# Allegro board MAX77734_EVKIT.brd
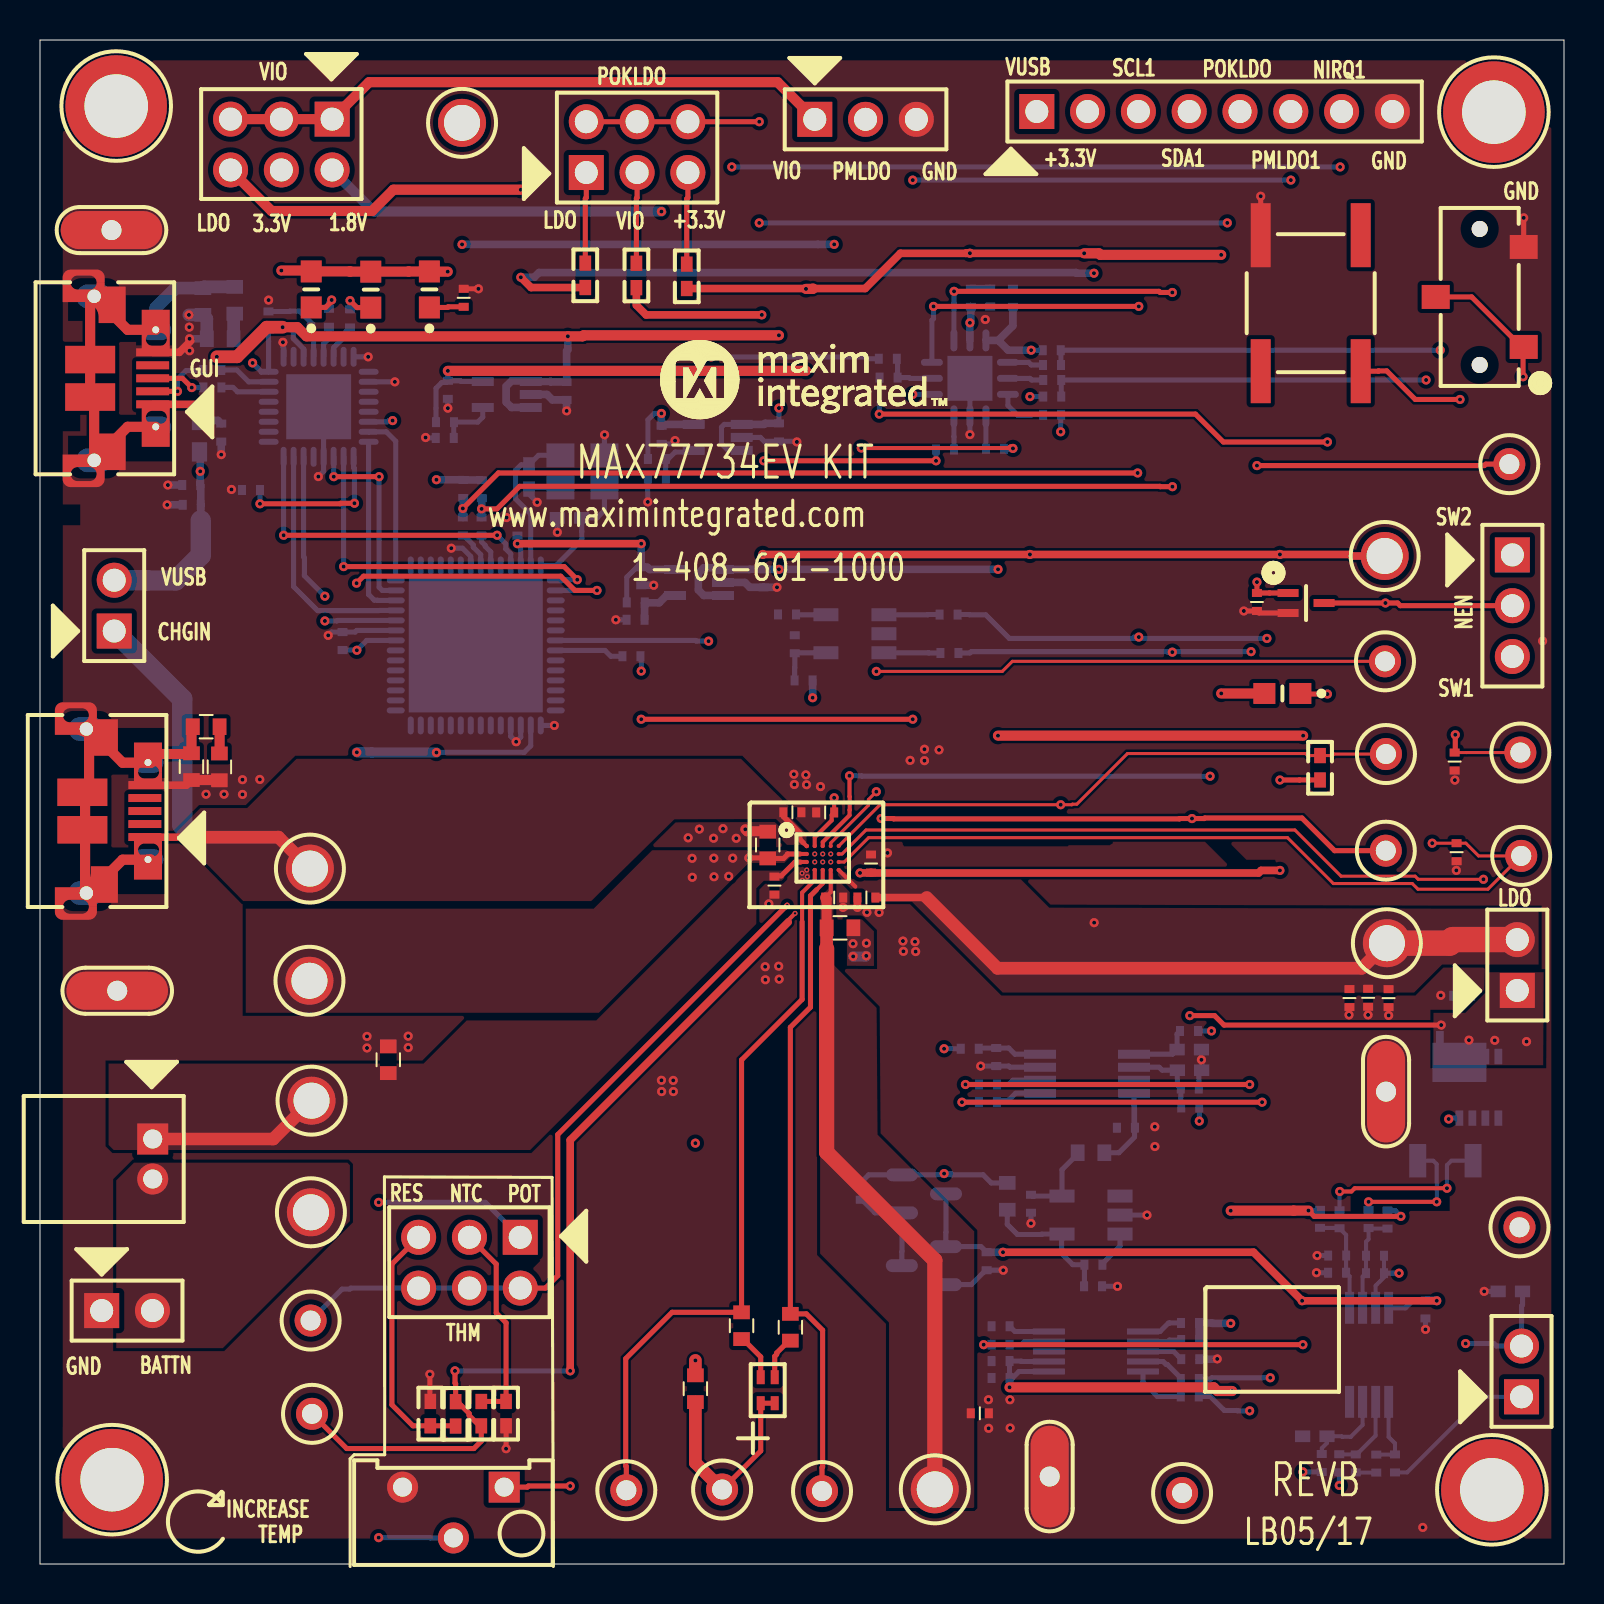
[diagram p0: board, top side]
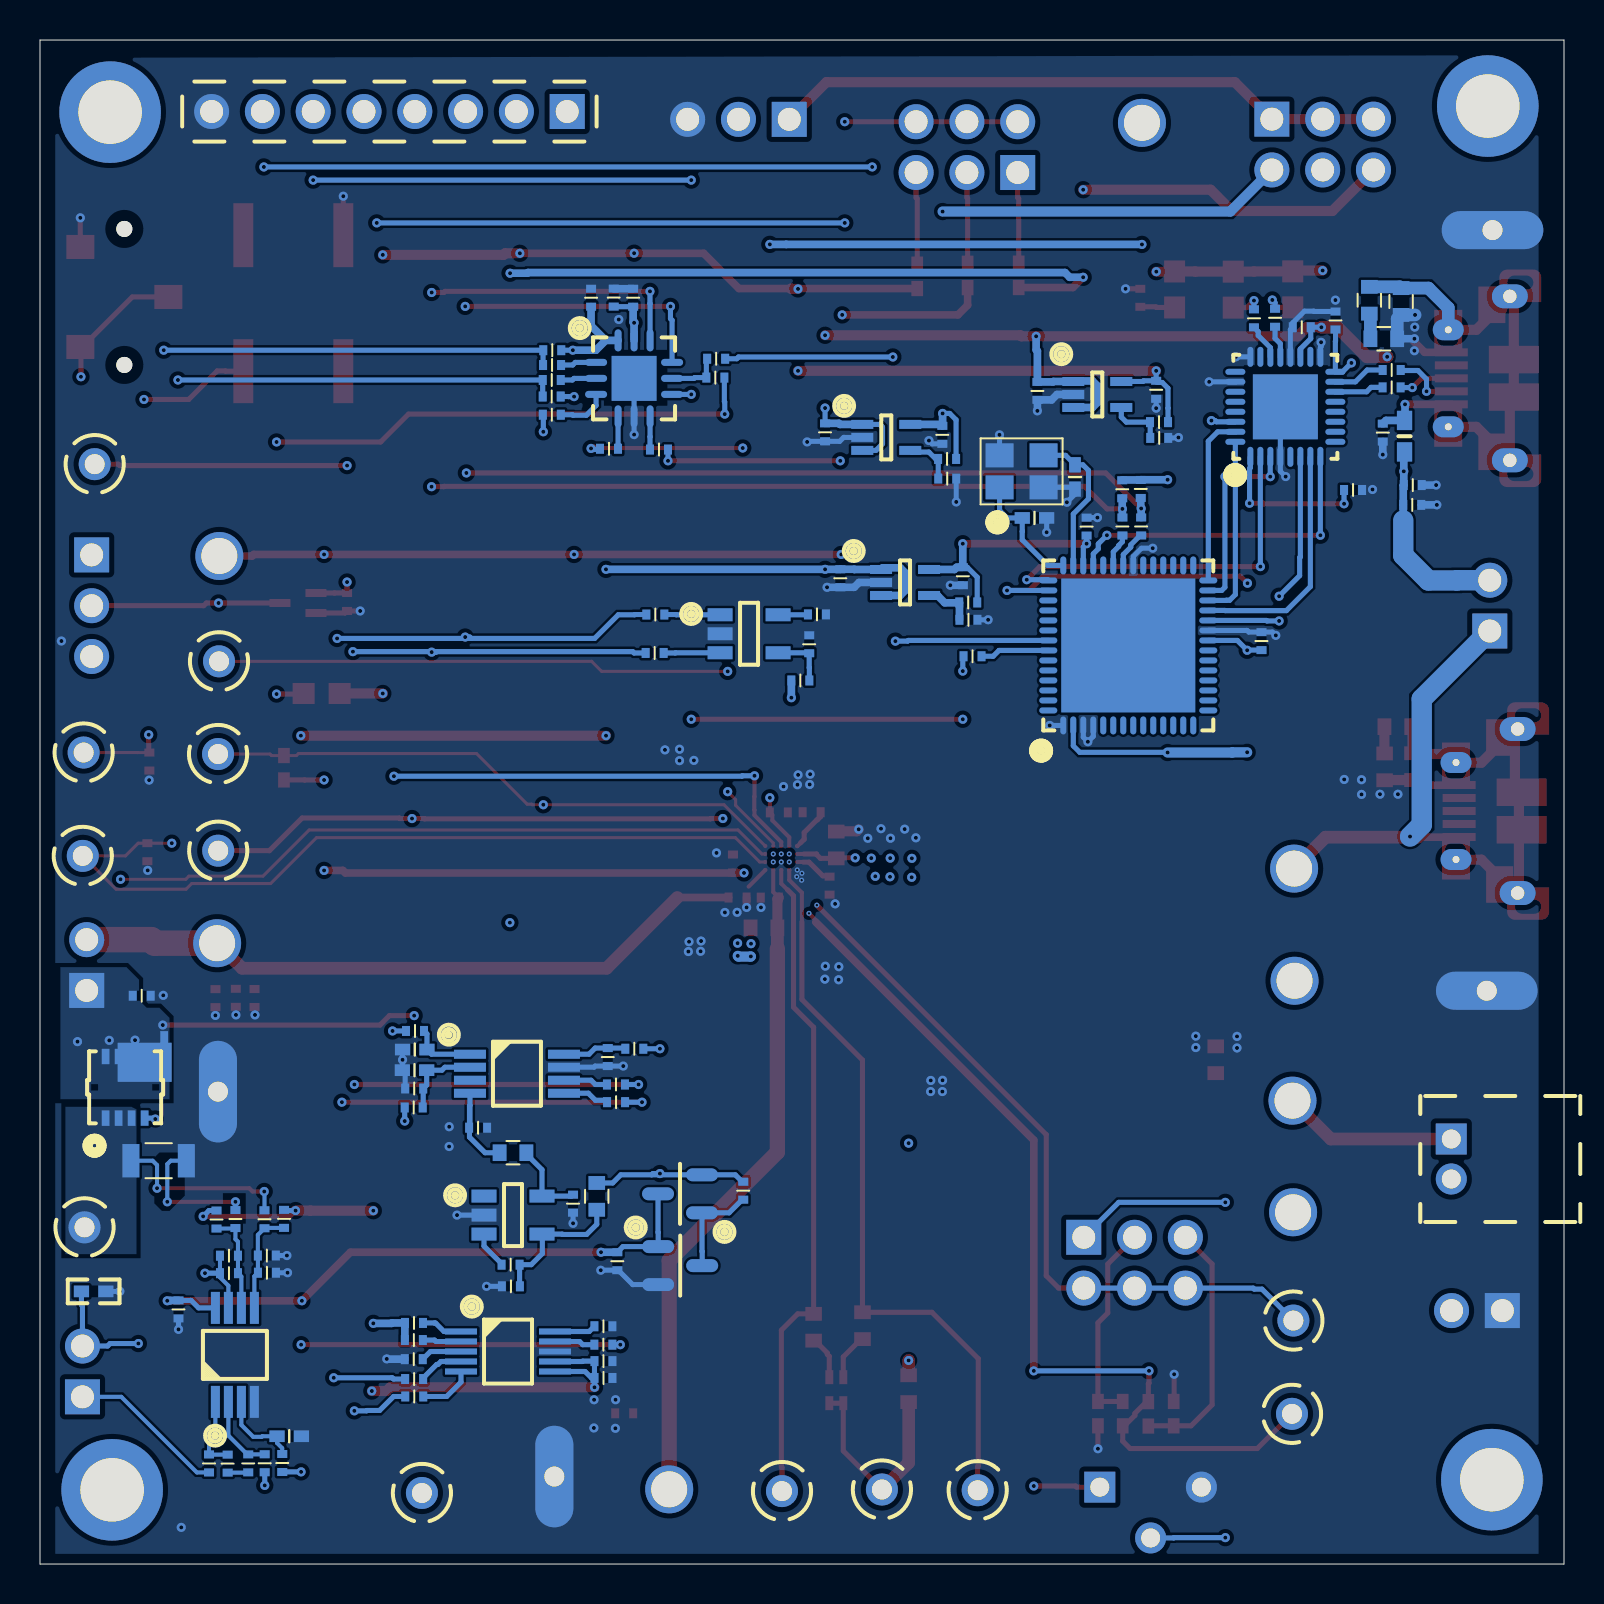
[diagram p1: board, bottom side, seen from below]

Outline 76.2 x 76.2 mm; copper layers: TOP, INTERNAL2, INTERNAL3, BOTTOM. Coordinates in mm from the lower left corner of the outline.
Outline path: 0,76.2 0,0 76.2,0 76.2,76.2 0,76.2

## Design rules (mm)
constraint set DEFAULT: min track width 0.102
net group NIRQ: nets NIRQ UNNAMED_4_EKRESSMD_I87_1
net group NIRQ1: nets NIRQ1 UNNAMED_4_EKRESSMD_I190_2
net group P01: nets P01 PMLDO1
net group PMLDO: nets PMLDO UNNAMED_4_EKRESSMD_I210_1
net group UNNAMED_1_10103592-0001LF_I54_SHIELD10: nets UNNAMED_1_10103592-0001LF_I54_SHIELD10 UNNAMED_1_EKCAPNP_I52_1
net group UNNAMED_4_10103592-0001LF_I2_2: nets UNNAMED_4_10103592-0001LF_I2_2 UNNAMED_4_EKRESSMD_I15_2
net group UNNAMED_4_10103592-0001LF_I2_3: nets UNNAMED_4_10103592-0001LF_I2_3 UNNAMED_4_EKRESSMD_I16_2
net group UNNAMED_4_10103592-0001LF_I2_SHIELD10: nets UNNAMED_4_10103592-0001LF_I2_SHIELD10 UNNAMED_4_EKCAPNP_I29_1
net group UNNAMED_4_EKRESSMD_I17_1: nets UNNAMED_4_EKRESSMD_I17_1 UNNAMED_4_EKRESSMD_I17_2
net group UNNAMED_4_EKRESSMD_I18_1: nets UNNAMED_4_EKRESSMD_I18_1 UNNAMED_4_EKRESSMD_I18_2
net group VUSB: nets UNNAMED_4_10103592-0001LF_I2_1 VUSB
net group SCL: nets SCL SDA UNNAMED_4_EKRESSMD_I153_1 UNNAMED_4_EKRESSMD_I154_1 UNNAMED_4_EKRESSMD_I171_2 VIO
net group SCL1: nets SCL1 UNNAMED_4_24AA02_I200_SCL UNNAMED_4_EKRESSMD_I109_1
net group SDA1: nets SDA1 UNNAMED_4_24AA02_I200_SDA UNNAMED_4_EKRESSMD_I113_1

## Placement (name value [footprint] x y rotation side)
AMUX  N/A  [TP_180P120D460H]  57.1 3.55 0 top
BATT  N/A  [TP_C240H180]  13.58 23.17 0 top
BATTN  N/A  [TP_C240H180]  13.55 17.59 0 top
C1  2.2UF  [0402#2]  37.62 37.59 180 top
C2  4.7UF  [0402#2]  36.72 33.92 270 top
C3  1UF  [0402#2]  39.26 37.58 0 top
C4  2.2UF  [0402#2]  41.32 33.32 0 top
C5  0.1UF  [CAPC1005X50L]  41.55 35.02 270 top
C6  22UF  [0603]  36.39 35.95 270 top
C7  10UF  [CAPC1005X50L]  39.71 33.32 180 top
C8  OPEN  [CAPC1005X50L]  46.99 7.54 180 top
C9  OPEN  [CAPC1005X50L]  65.47 28.3 90 top
C10  0.47UF  [CAPC1608X90L]  8.97 39.86 270 top
C11  0.1UF  [CAPC1005X50L]  66.41 28.31 90 top
C12  0.01UF  [CAPC1005X50L]  67.43 28.29 90 top
C14  0.1UF  [CAPC1005X50L]  37.74 45.99 270 bottom
C15  1UF  [0603]  17.41 25.21 270 top
C108  0.1UF  [CAPC1005X50L]  13.11 61.84 180 bottom
C110  1UF  [CAPC1005X50L]  36.95 56.58 90 bottom
C111  1UF  [CAPC1005X50L]  31.08 56.46 90 bottom
C112  1UF  [CAPC1005X50L]  36.18 49.29 90 bottom
C113  1UF  [CAPC1005X50L]  30.06 49.39 90 bottom
C114  0.47UF  [CAPC1608X90L]  9.01 61.26 180 bottom
C115  1UF  [CAPC1005X50L]  46.54 63.32 270 bottom
C118  1UF  [CAPC1005X50L]  26.33 58.65 90 bottom
C120  1UF  [CAPC1005X50L]  48.65 63.31 270 bottom
C129  OPEN  [CAPC1005X50L]  70.73 40.12 90 top
C134  OPEN  [CAPC1005X50L]  70.83 35.59 90 top
C150  0.1UF  [CAPC1005X50L]  15.13 46.15 90 bottom
C151  0.1UF  [CAPC1005X50L]  23.87 51.87 90 bottom
C152  15PF  [0402]  26.48 52.3 0 bottom
C153  15PF  [0402]  24.45 54.35 90 bottom
C154  4.7UF  [CAPC1005X50L]  7.56 53.95 0 bottom
C155  0.1UF  [CAPC1005X50L]  9.06 56.57 270 bottom
C156  0.1UF  [CAPC1005X50L]  11.42 62.18 270 bottom
C157  0.1UF  [CAPC1005X50L]  47.51 63.32 270 bottom
C158  1UF  [CAPC1005X50L]  20.39 58.71 90 bottom
C159  0.1UF  [CAPC1005X50L]  10.55 53.7 180 bottom
C216  1000PF  [CAPC1005X50L]  65.79 5.03 270 bottom
C217  0.1UF  [CAPC1005X50L]  69.27 12.73 270 bottom
C218  18PF  [0402#2]  64.86 15.42 0 bottom
C219  18PF  [0402#2]  66.75 14.54 180 bottom
C220  4700PF  [0402]  57.48 24.69 180 bottom
C221  0.1UF  [CAPC1005X50L]  48.03 9.3 0 bottom
C222  0.1UF  [CAPC1005X50L]  48.03 10.14 0 bottom
C223  0.1UF  [CAPC1005X50L]  48.03 11.89 0 bottom
C234  0.1UF  [CAPC1005X50L]  52.65 13.88 180 bottom
C235  0.1UF  [CAPC1005X50L]  49.55 18.02 90 bottom
C237  0.1UF  [CAPC1005X50L]  47.81 25.35 90 bottom
C242  1UF  [CAPC1005X50L]  71.11 28.41 0 bottom
C244  0.1UF  [CAPC1005X50L]  54.3 21.82 180 bottom
C249  4700PF  [0402]  57.46 25.72 180 bottom
C251  4700PF  [0402]  63.74 6.39 0 bottom
CHGIN  N/A  [TP_C240H180]  13.5 34.77 0 top
D1  HSMF-C163  [LED_HSMF-C16X]  36.39 8.69 90 top
D100  LTST-C190YKT  [LEDC1608X80M]  16.54 63.72 90 top
D101  LTST-C190YKT  [LEDC1608X80M]  13.56 63.73 90 top
D102  LTST-C190CKT  [LEDC1608X80M]  19.47 63.73 90 top
D103  LTST-C190CKT  [LEDC1608X80M]  62.12 43.53 180 top
EN_EXT  N/A  [TP_180P120D460H]  73.47 54.99 0 top
FB100  220  [0603#2]  7.97 56.39 270 bottom
GND1  MAXIMPAD  [EVK_MAXIMPAD]  3.86 28.66 0 top
GND2  MAXIMPAD  [EVK_MAXIMPAD]  67.3 23.62 90 top
GND3  MAXIMPAD  [EVK_MAXIMPAD]  3.58 66.69 0 top
GND4  MAXIMPAD  [EVK_MAXIMPAD]  50.48 4.37 90 top
IN_SINK  N/A  [TP_180P120D460H]  34.1 3.72 0 top
INLDO  N/A  [TP_C240H180]  44.74 3.73 0 top
J1  10103592-0001LF  [FCI_10103592-0001LF]  2.32 37.65 270 top
J2  TSW-103-07-T-S  [SAMTEC_TSW-103-07-T-S]  38.74 72.23 0 top
J3  TSW-102-07-T-S  [SAMTEC_TSW-102-07-X-S]  3.71 46.65 90 top
J4  TSW-102-07-T-S  [SAMTEC_TSW-102-07-X-S]  3.08 12.67 0 top
J5  TSW-103-07-T-S  [SAMTEC_TSW-103-07-T-S]  73.62 50.46 270 top
J6  TSW-103-07-L-D  [SAMTEC_TSW-103-07-X-D]  27.31 69.57 0 top
J7  TSW-103-07-L-D  [SAMTEC_TSW-103-07-X-D]  24.01 16.33 180 top
J8  10103592-0001LF  [FCI_10103592-0001LF]  2.71 59.28 270 top
J9  S2B-PH-K-S(LF)(SN)  [JST_S2B-PH-K-X]  5.64 21.25 90 top
J100  PEC08SAAN  [SULLINS_PXC08SAAN]  49.84 72.62 0 top
J101  TSW-103-07-L-D  [SAMTEC_TSW-103-07-X-D]  14.61 72.24 180 top
J206  TSW-102-07-T-S  [SAMTEC_TSW-102-07-X-S]  74.08 8.36 90 top
J207  TSW-102-07-T-S  [SAMTEC_TSW-102-07-X-S]  73.87 28.68 90 top
LDO  N/A  [TP_C240H180]  67.34 31.04 0 top
NEN  N/A  [TP_180P120D460H]  67.25 45.13 0 top
NIRQ  N/A  [TP_180P120D460H]  67.3 40.5 0 top
NOREF  -  []  0 76.2 0 top
NOREF#2  -  []  49.43 129.9 0 top
NOREF#3  -  [unnamed#2]  3.81 72.9 0 top
NOREF#4  -  [unnamed#2]  3.61 4.22 0 top
NOREF#5  -  []  33.04 59.14 0 top
NOREF#6  -  [unnamed#2]  72.69 72.59 0 top
NOREF#7  -  []  -23.98 68.78 0 top
NOREF#8  -  []  108.1 68.78 0 top
NOREF#9  -  []  108.1 -30.28 0 top
NOREF#10  -  []  0 0 90 top
NOREF#11  -  []  13.08 -8.56 0 top
NOREF#12  -  [unnamed#2]  72.59 3.71 0 top
POKLDO  N/A  [TP_180P120D460H]  67.29 35.67 0 top
Q1  FDY300NZ  [SOT50P160X90-3M]  63.3 48.05 0 top
Q203  IRFHM8337TRPBF  [TRAN_IRF_PQFN8_SINGLE_B]  71.94 23.83 90 bottom
Q205  FDN360P  [SOT95P237X112-3M]  44.2 18.51 0 bottom
Q206  2N7002  [SOT95P237X112-3M]  44.19 14.92 180 bottom
R1  10K  [0402]  22.06 7.52 90 top
R2  100K  [0402]  27.27 64.43 90 top
R3  0  [RESC1608X90L]  8.31 41.87 0 top
R4  1M  [RESC1608X90L]  7.57 39.87 270 top
R5  0  [0603]  32.77 8.77 270 top
R6  100K  [0402]  29.82 64.43 90 top
R7  0  [0603]  35.08 11.92 90 top
R8  0  [0603]  37.52 11.84 90 top
R9  100K  [0402]  64 39.81 90 top
R10  100K  [0402#2]  60.85 48.1 270 top
R11  100K  [0402]  32.34 64.38 90 top
R12  200K  [BOURNS_3296Y]  20.67 2.57 0 top
R13  10K  [0402]  19.52 7.52 90 top
R14  0  [0603]  40 31.81 0 top
R15  10K  [0402]  20.78 7.51 270 top
R100  4.7K  [RESC1005X50L]  22.09 53.74 90 bottom
R103  22  [RESC1005X50L]  8.62 58.83 0 bottom
R107  2.2K  [RESC1005X50L]  50.61 58.37 0 bottom
R108  2.2K  [RESC1005X50L]  50.59 60.69 0 bottom
R109  100  [RESC1005X50L]  14.45 62.31 90 bottom
R110  470  [0402#2]  21.18 63.31 90 top
R111  100  [RESC1005X50L]  15.5 62.28 90 bottom
R115  100K  [RESC1005X50L]  7.59 52.96 180 bottom
R118  4.7K  [RESC1005X50L]  21.16 53.75 90 bottom
R122  1M  [RESC1608X90L]  8.15 63.12 270 bottom
R123  22  [RESC1005X50L]  8.62 59.7 0 bottom
R132  100K  [RESC1005X50L]  29.57 45.39 0 bottom
R133  0  [RESC1005X50L]  47.75 55.76 0 bottom
R135  0  [RESC1005X50L]  50.6 59.95 0 bottom
R136  0  [RESC1005X50L]  50.61 59.2 0 bottom
R142  0  [RESC1608X90L]  9.73 63.19 270 bottom
R143  0  [RESC1005X50L]  45.25 55.72 0 bottom
R148  0  [RESC1005X50L]  22.08 51.88 90 bottom
R150  22  [RESC1005X50L]  50.61 57.46 0 bottom
R151  150  [0402#2]  42.43 59.32 0 bottom
R152  0  [RESC1005X50L]  42.39 60.26 0 bottom
R155  0  [RESC1005X50L]  21.14 51.88 90 bottom
R156  105K  [0402#2]  29.79 48.08 0 bottom
R157  100K  [RESC1005X50L]  29.78 47.21 180 bottom
R158  169K  [0402#2]  20.25 57.09 0 bottom
R159  100K  [RESC1005X50L]  20.24 56.3 180 bottom
R160  47.5K  [0402#2]  30.85 55.25 0 bottom
R161  100K  [RESC1005X50L]  30.84 54.27 180 bottom
R162  0  [RESC1005X50L]  45.43 47.47 180 bottom
R163  0  [RESC1005X50L]  38.18 44.18 0 bottom
R164  0  [RESC1005X50L]  45.47 45.55 0 bottom
R165  0  [RESC1005X50L]  37.35 47.48 180 bottom
R210  0  [RESC1005X50L]  48.03 10.97 180 bottom
R211  0  [RESC1005X50L]  57.51 10.24 180 bottom
R212  0  [RESC1005X50L]  57.49 8.38 180 bottom
R213  0  [RESC1005X50L]  57.49 9.25 180 bottom
R214  100K  [RESC1005X50L]  57.51 11.2 180 bottom
R248  100  [0402#2]  66.82 5.02 90 bottom
R249  680  [0402#2]  64.97 5.04 270 bottom
R250  20K  [0402#2]  64.09 5.05 90 bottom
R251  0  [RESC1005X50L]  67.75 5.03 270 bottom
R252  4.99K  [0402#2]  64.85 14.56 0 bottom
R253  4.99K  [0402#2]  66.75 15.42 180 bottom
R254  1K  [RESC1005X50L]  64.98 17.24 90 bottom
R255  1K  [RESC1005X50L]  66.43 17.25 90 bottom
R257  1M  [0402]  73.52 13.63 180 bottom
R258  1  [1206]  70.27 20.16 180 bottom
R259  0  [RESC1005X50L]  57.51 22.83 180 bottom
R260  OPEN  [RESC1005X50L]  57.49 23.77 0 bottom
R277  0  [RESC1608X90L]  48.36 18.38 270 bottom
R279  0  [RESC1608X90L]  52.55 20.56 0 bottom
R280  100K  [RESC1005X50L]  52.67 14.97 0 bottom
R283  100K  [RESC1005X50L]  57.5 12.05 180 bottom
R285  0  [RESC1005X50L]  57.45 26.65 180 bottom
R286  0  [RESC1005X50L]  46.48 25.76 0 bottom
R287  10K  [0402#2]  47.33 15.14 270 bottom
R288  10K  [0402#2]  41.04 18.67 270 bottom
R299  470K  [0402#2]  64 17.26 90 bottom
R300  649K  [0402#2]  67.38 17.22 270 bottom
R303  0  [RESC1005X50L]  47.4 23.98 0 bottom
R304  0  [RESC1005X50L]  47.4 23.09 0 bottom
RT1  10K  [0402]  23.3 7.52 270 top
SCL  N/A  [TP_180P120D460H]  74.06 35.41 0 top
SDA  N/A  [TP_180P120D460H]  74.02 40.57 0 top
SINK1  N/A  [TP_180P120D460H]  29.32 3.69 0 top
SINK2  N/A  [TP_180P120D460H]  39.1 3.65 0 top
SNS  N/A  [TP_180P120D460H]  73.97 16.83 0 top
SW1  EVQ-Q2K03W  [SW_EVQ-Q2X03W]  63.54 63.04 90 top
SW2  CL-SB-12B-11  [SW_CL-SB-12B-1X]  71.98 63.35 180 top
SYS  N/A  [TP_C240H180]  13.47 29.16 0 top
TBIAS  N/A  [TP_180P120D460H]  13.6 7.51 90 top
THM  N/A  [TP_180P120D460H]  13.53 12.17 90 top
U1  MAX77734  [EK_MAX77734]  39.14 35.3 0 top
U100  MAXQ2000-RBX+  [QFN50P800X800X80-57M]  21.79 45.93 90 bottom
U101  FT232RQ  [QFN50P500X500X100-33V2M]  13.93 57.86 90 bottom
U102  MAX8512EXK  [SOT65P210X110-5M]  23.34 58.48 180 bottom
U103  MAX8512EXK  [SOT65P210X110-5M]  33.89 56.33 180 bottom
U104  MAX8512EXK  [SOT65P210X110-5M]  32.95 49.08 180 bottom
U107  MAX3395EETC  [QFN80P400X400X80-13M]  46.5 59.28 180 bottom
U108  24AA02T-I/OT  [SOT95P280X145-5M]  40.75 46.51 180 bottom
U203  MAX44251AUA+  [SOP65P490X110-8M]  66.46 10.46 90 bottom
U205  MAX5805AAUB+  [SOP50P490X110-10M]  52.8 10.62 180 bottom
U209  MAX11644EUA+  [SOP65P490X110-8M]  52.35 24.51 180 bottom
U210  MAX6037BAUK41+  [SOT95P280X145-5M]  52.55 17.44 180 bottom
VIO  N/A  [TP_C240H180]  67.23 50.4 0 top
VL  N/A  [TP_C240H180]  21.1 72.06 0 top
Y101  16MHZ  [XTAL320X250X070M]  27.12 54.63 180 bottom

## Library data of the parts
AMUX EN_EXT NEN NIRQ POKLDO SCL SDA = TP: part number: TP_TP-TP_180P120D460H,N/A,02-TPMINI5002-00
BATT BATTN CHGIN INLDO LDO SYS VIO VL = TP: alternate symbols: TP_C340H160L; part number: TP_TP-TP_C240H180,N/A,02-TPMINI5010-00
C1 = CAP_NP: alternate symbols: 0402_NOSILK,CAPC1005X50L; part number: CAP_NP_0402CAP-0402,2.2UF,20-002U2-Z51
C2 = CAP_NP: alternate symbols: 0402_NOSILK,CAPC1005X50L; part number: CAP_NP_0402CAP-0402,4.7UF,20-004U7-CA54
C3 = CAP_NP: alternate symbols: 0402_NOSILK,CAPC1005X50L; part number: CAP_NP_0402CAP-0402,1UF,20-0001U-BA24
C4 = CAP_NP: alternate symbols: 0402_NOSILK,CAPC1005X50L; part number: CAP_NP_0402CAP-0402,2.2UF,20-002U2-A52
C5 C11 = EK_CAP_NP: part number: EK_CAP_NP_0402_FF-CAPC1005X50L,0.1UF,20-000U1-33
C6 = CAP_NP: alternate symbols: 0603_NOSILK,CAPC1608X90L; part number: CAP_NP_0603CAP-0603,22UF,20-0022U-X3
C7 = EK_CAP_NP: part number: EK_CAP_NP_0402_FF-CAPC1005X50L,10UF,20-0010U-B65
C8 C9 = EK_CAP_NP: alternate symbols: 0402,0402_NOSILK; part number: EK_CAP_NP_0402_FF-CAPC1005X50L,OPEN,N/A
C10 C114 = EK_CAP_NP: part number: EK_CAP_NP_0603_FF-CAPC1608X90L,0.47UF,20-00U47-16; signal model: DEFAULT_CAPACITOR_470000pF_2_1
C12 = EK_CAP_NP: part number: EK_CAP_NP_0402_FF-CAPC1005X50L,0.01UF,20-00U01-19A
C14 C156 C157 = EK_CAP_NP: part number: EK_CAP_NP_0402_FF-CAPC1005X50L,0.1UF,20-000U1-12; signal model: DEFAULT_CAPACITOR_100000pF_2_1
C15 = CAP_NP: alternate symbols: 0603_NOSILK,CAPC1608X90L; part number: CAP_NP_0603CAP-0603,1UF,20-0001U-16
C108 C150 C151 C155 C159 C217 C221-C223 C234 C235 C237 C244 = EK_CAP_NP: part number: EK_CAP_NP_0402_FF-CAPC1005X50L,0.1UF,20-000U1-12
C110-C113 C115 C118 C120 C158 C242 = EK_CAP_NP: part number: EK_CAP_NP_0402_FF-CAPC1005X50L,1UF,20-0001U-B65
C129 C134 = EK_CAP_NP: alternate symbols: 0402,0402_NOSILK; part number: EK_CAP_NP_0402_FF-CAPC1005X50L,OPEN,N/A; signal model: DEFAULT_CAPACITOR_0.001pF_2_1
C152 C153 = CAP_NP: alternate symbols: 0402_NOSILK,CAPC1005X50L; part number: CAP_NP_0402CAP-0402,15PF,20-0015P-F3
C154 = EK_CAP_NP: part number: EK_CAP_NP_0402_FF-CAPC1005X50L,4.7UF,20-004U7-33A; signal model: DEFAULT_CAPACITOR_4.7e+06pF_2_1
C216 = EK_CAP_NP: part number: EK_CAP_NP_0402_FF-CAPC1005X50L,1000PF,20-1000P-E7
C218 C219 = CAP_NP: alternate symbols: 0402_NOSILK,CAPC1005X50L; part number: CAP_NP_0402CAP-0402,18PF,20-0018P-27
C220 C249 C251 = CAP_NP: alternate symbols: (0402_NOSILK); part number: CAP_NP_0402CAP-0402,4700PF,20-4700P-A0Z
D1 = LED_4P: part number: LED_4P_RED-GREEN-LED_HSMF-C16X,HSMF-C163,30-HSMFC163-00
D100 D101 = LED: part number: LED_LEDC1608X80M-LEDC1608X80M,LTST-C190YKT,30-LTSTC190YKT-00
D102 D103 = LED: part number: LED_LEDC1608X80M-LEDC1608X80M,LTST-C190CKT,30-LTSTC190CKT-00
FB100 = INDUCT: alternate symbols: (0603_NOSILK); part number: INDUCT_0603-0603,220,50-00220-SM12A; signal model: DEFAULT_INDUCTOR_220.000000nH_1_2
GND1-GND4 = EVK_MAXIMPAD: alternate symbols: EVK_MAXIMPAD_ALT; part number: EVK_MAXIMPAD_MISC-EVK_MAXIMPAD,MAXIMPAD,01-9020BUSS20AWG-00
IN_SINK SINK1 SINK2 SNS TBIAS THM = TP: part number: TP_TP-TP_180P120D460H,N/A,02-TPMINI5000-00
J1 J8 = 10103592-0001LF: part number: 10103592-0001LF_SMT-FCI_10103592-0001LF,10103592-0001LF,01-101035920001LF5P-26
J2 J5 = HEADER_3P: part number: HEADER_3P_SIP-SAMTEC_TSW-103-07-T-S,TSW-103-07-T-S,01-TSW10307TS3P-17
J3 J4 J206 J207 = HEADER_2P: part number: HEADER_2P_TH-SAMTEC_TSW-102-07-X-S,TSW-102-07-T-S,01-TSW10207TS2P-17
J6 J7 J101 = HEADER_3P_X_2R: part number: HEADER_3P_X_2R_TH-SAMTEC_TSW-103-07-X-D,TSW-103-07-L-D,01-TSW10307LD6P-19
J9 = HEADER_2P: part number: HEADER_2P_RA-JST_S2B-PH-K-X,S2B-PH-K-S(LF)(SN),01-S2BPHKS2P-19
J100 = HEADER_8P: part number: HEADER_8P_TH-SULLINS_PXC08SAAN,PEC08SAAN,01-PEC08SAAN8P-21
Q1 = TRAN_NCH_3P: part number: TRAN_NCH_3P_SC89_TRENCH-SOT50P160X90-3M,FDY300NZ,90-FDY300NZ-28
Q203 = TRAN_NCH_8P: part number: TRAN_NCH_8P_PQFN8-TRAN_IRF_PQFN8_SINGLE_B,IRFHM8337TRPBF,90-IRFHM8337-10
Q205 = TRAN_PCH_3P: part number: TRAN_PCH_3P_SOT-23-SOT95P237X112-3M,FDN360P,90-FDC360P-25
Q206 = TRAN_NCH_3P: part number: TRAN_NCH_3P_SOT23-SOT95P237X112-3M,2N7002,90-2N7002-06
R1 R13 R15 R287 R288 = RES: alternate symbols: 0402_NOSILK,RESC1005X50L,RES0402-NOT_FOR_TEST; part number: RES_0402RES-0402,10K,80-0010K-23
R2 R6 R9-R11 = RES: alternate symbols: 0402_NOSILK,RESC1005X50L; part number: RES_0402RES-0402,100K,80-0100K-23
R3 R142 = EK_RES_SMD: part number: EK_RES_SMD_0603_FF-RESC1608X90L,0,80-0000R-27; signal model: DEFAULT_RESISTOR_0.001OHM_2_1
R4 R122 = EK_RES_SMD: part number: EK_RES_SMD_0603_FF-RESC1608X90L,1M,80-0001M-19; signal model: DEFAULT_RESISTOR_0.001OHM_2_1
R5 R7 R8 R14 = RES: alternate symbols: 0603_NOSILK,RESC1608X90L; part number: RES_0603RES-0603,0,80-0000R-AA6
R12 = RES_POT: part number: RES_POT_POT-BOURNS_3296Y,200K,80-0200K-F0A
R100 R118 = EK_RES_SMD: part number: EK_RES_SMD_0402_FF-RESC1005X50L,4.7K,80-004K7-23; signal model: DEFAULT_RESISTOR_4700OHM_2_1
R103 R123 = EK_RES_SMD: part number: EK_RES_SMD_0402_FF-RESC1005X50L,22,80-0022R-23; signal model: DEFAULT_RESISTOR_22.000000OHM_1_2
R107 R108 = EK_RES_SMD: part number: EK_RES_SMD_0402_FF-RESC1005X50L,2.2K,80-002K2-23; signal model: DEFAULT_RESISTOR_470.000000OHM_1_2
R109 R111 = EK_RES_SMD: part number: EK_RES_SMD_0402_FF-RESC1005X50L,100,80-0100R-23; signal model: DEFAULT_RESISTOR_100.000000OHM_2_1
R110 = RES: alternate symbols: (0402_NOSILK,RESC1005X50L); part number: RES_0402RES-0402,470,80-0470R-23
R115 R132 = EK_RES_SMD: part number: EK_RES_SMD_0402_FF-RESC1005X50L,100K,80-0100K-23; signal model: DEFAULT_RESISTOR_100000OHM_1_2
R133 R135 R136 R148 R152 R155 R162-R165 = EK_RES_SMD: part number: EK_RES_SMD_0402_FF-RESC1005X50L,0,80-0000R-26; signal model: DEFAULT_RESISTOR_22.000000OHM_2_1
R143 = EK_RES_SMD: part number: EK_RES_SMD_0402_FF-RESC1005X50L,0,80-0000R-26; signal model: DEFAULT_RESISTOR_0.001OHM_1_2
R150 = EK_RES_SMD: part number: EK_RES_SMD_0402_FF-RESC1005X50L,22,80-0022R-23; signal model: DEFAULT_RESISTOR_22.000000OHM_2_1
R151 = RES: alternate symbols: (0402_NOSILK,RESC1005X50L); part number: RES_0402RES-0402,150,80-0150R-23
R156 = RES: alternate symbols: (0402_NOSILK,RESC1005X50L); part number: RES_0402RES-0402,105K,80-0105K-18
R157 R159 R161 R214 R280 R283 = EK_RES_SMD: part number: EK_RES_SMD_0402_FF-RESC1005X50L,100K,80-0100K-23
R158 = RES: alternate symbols: (0402_NOSILK,RESC1005X50L); part number: RES_0402RES-0402,169K,80-0169K-23
R160 = RES: alternate symbols: (0402_NOSILK,RESC1005X50L); part number: RES_0402RES-0402,47.5K,80-047K5-23
R210-R213 R251 R259 R285 R286 R303 R304 = EK_RES_SMD: part number: EK_RES_SMD_0402_FF-RESC1005X50L,0,80-0000R-26
R248 = RES: alternate symbols: 0402_NOSILK,RESC1005X50L,RES0402-NOT_FOR_TEST; part number: RES_0402RES-0402,100,80-0100R-23
R249 = RES: alternate symbols: (0402_NOSILK,RESC1005X50L); part number: RES_0402RES-0402,680,80-0680R-23
R250 = RES: alternate symbols: 0402_NOSILK,RESC1005X50L,RES0402-NOT_FOR_TEST; part number: RES_0402RES-0402,20K,80-0020K-23
R252 R253 = RES: alternate symbols: (0402_NOSILK,RESC1005X50L); part number: RES_0402RES-0402,4.99K,80-04K99-23
R254 R255 = EK_RES_SMD: part number: EK_RES_SMD_0402_FF-RESC1005X50L,1K,80-0001K-23
R257 = RES: alternate symbols: (0402_NOSILK,RESC1005X50L); part number: RES_0402RES-0402,1M,80-0001M-23
R258 = RES: alternate symbols: RESC3116X60L; part number: RES_1206RES-1206,1,80-0001R-AA55
R260 = EK_RES_SMD: alternate symbols: 0402,0402_NOSILK,; part number: EK_RES_SMD_0402_FF-RESC1005X50L,OPEN,N/A
R277 R279 = EK_RES_SMD: part number: EK_RES_SMD_0603_FF-RESC1608X90L,0,80-0000R-27
R299 = RES: alternate symbols: (0402_NOSILK,RESC1005X50L); part number: RES_0402RES-0402,470K,80-0470K-23
R300 = RES: alternate symbols: 0402_NOSILK,RESC1005X50L; part number: RES_0402RES-0402,649K,80-0649K-AA18
RT1 = THERMISTOR_SMD: part number: THERMISTOR_SMD_0402-0402,10K,83-0010K-23A
SW1 = EVQ-Q2XXXX: part number: EVQ-Q2XXXX_SMT-SW_EVQ-Q2X03W,EVQ-Q2K03W,11-EVQQ2K03W-00
SW2 = CL-SB-12B-1X: part number: CL-SB-12B-1X_SMD-SW_CL-SB-12B-1X,CL-SB-12B-11,11-CLSB12B11-00
U1 = EK_MAX77734: part number: EK_MAX77734_BGA20-EK_MAX77734,MAX77734,N/A
U100 = MAXQ2000: part number: MAXQ2000_TQFN56-EP-QFN50P800X800X80-57M,MAXQ2000-RBX+,10-MAXQ2000RBX-T
U101 = FT232RQ: part number: FT232RQ_QFN32-EP-QFN50P500X500X100-33V2M,FT232RQ,10-FT232RQ-G
U102-U104 = MAX8512: part number: MAX8512_SC70-SOT65P210X110-5M,MAX8512EXK,10-MAX8512EXK-X
U107 = MAX3395E: part number: MAX3395E_TQFN-QFN80P400X400X80-13M,MAX3395EETC,10-MAX3395EETC-T
U108 = 24AA02: part number: 24AA02_SOT23-5-SOT95P280X145-5M,24AA02T-I/OT,10-24AA02TIOT-U
U203 = MAX44251: part number: MAX44251_SPLIT_UMAX8-SOP65P490X110-8M,MAX44251AUA+,10-MAX44251AUA-U
U205 = MAX5805: part number: MAX5805_UMAX10-SOP50P490X110-10M,MAX5805AAUB+,10-MAX5805AAUB-U
U209 = MAX11644: part number: MAX11644_UMAX8-SOP65P490X110-8M,MAX11644EUA+,10-MAX11644EUA-U
U210 = MAX6037: part number: MAX6037_SOT23-5-SOT95P280X145-5M,MAX6037BAUK41+,10-MAX6037BAUK41-U
Y101 = XTAL: part number: XTAL_XTAL320X250X070M-XTAL320X250X070M,16MHZ,60-0016M-26A

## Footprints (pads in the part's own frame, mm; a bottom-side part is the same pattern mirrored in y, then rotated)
0402
  rect 0.762x0.584 smd: 1(-0.61,0) 2(0.61,0)
0402#2
  rect 0.4x0.5 smd: 1(-0.45,0) 2(0.45,0)
0603
  rect 0.69x0.83 smd: 1(-0.67,0) 2(0.67,0)
0603#2
  rect 0.965x0.762 smd: 1(-0.787,0) 2(0.787,0)
1206
  rect 0.85x1.67 smd: 1(-1.385,0) 2(1.385,0)
BOURNS_3296Y
  rect 1.55x1.55 hole 0.95: 1(2.54,1.27)
  round 1.55 hole 0.95: 2(0,-1.27) 3(-2.54,1.27)
CAPC1005X50L
  rect 0.4x0.5 smd: 1(-0.45,0) 2(0.45,0)
CAPC1608X90L
  rect 0.69x0.83 smd: 1(-0.67,0) 2(0.67,0)
EK_MAX77734
  round 0.21 smd: A1(-0.8,0.6) A2(-0.4,0.6) A3(0,0.6) A4(0.4,0.6) A5(0.8,0.6) B1(-0.8,0.2) B2(-0.4,0.2) B3(0,0.2) B4(0.4,0.2) B5(0.8,0.2) C1(-0.8,-0.2) C2(-0.4,-0.2) C3(0,-0.2) C4(0.4,-0.2) C5(0.8,-0.2) D1(-0.8,-0.6) D2(-0.4,-0.6) D3(0,-0.6) D4(0.4,-0.6) D5(0.8,-0.6)
EVK_MAXIMPAD
  oval 5.08x1.905 hole 1: 1(0,0)
FCI_10103592-0001LF
  rect 0.4x1.65 smd: 1(1.3,2.925) 2(0.65,2.925) 3(0,2.925) 4(-0.65,2.925) 5(-1.3,2.925)
  custom 0.669x0.669 hole 0.7x1.3: 6(-4.1,0) 9(4.1,0)
  custom 0.35x0.35 hole 1.05x0.65: 7(-2.425,3.08) 8(2.425,3.08)
  rect 1.375x2.5 smd: 10(0.938,-0.2) 11(-0.938,-0.2)
JST_S2B-PH-K-X
  rect 1.55x1.55 hole 0.95: 1(0,0)
  round 1.55 hole 0.95: 2(-2,0)
LED_HSMF-C16X
  rect 0.7x0.4 smd: 1(-0.65,0.35) 2(-0.65,-0.35) 3(0.65,0.35) 4(0.65,-0.35)
LEDC1608X80M
  rect 1.1x1.05 smd: A(0.9,0) K(-0.9,0)
QFN50P500X500X100-33V2M
  oval 1x0.3 smd: 1(-2.5,1.75) 2(-2.5,1.25) 3(-2.5,0.75) 4(-2.5,0.25) 5(-2.5,-0.25) 6(-2.5,-0.75) 7(-2.5,-1.25) 8(-2.5,-1.75) 17(2.5,-1.75) 18(2.5,-1.25) 19(2.5,-0.75) 20(2.5,-0.25) 21(2.5,0.25) 22(2.5,0.75) 23(2.5,1.25) 24(2.5,1.75)
  oval 0.3x1 smd: 9(-1.75,-2.5) 10(-1.25,-2.5) 11(-0.75,-2.5) 12(-0.25,-2.5) 13(0.25,-2.5) 14(0.75,-2.5) 15(1.25,-2.5) 16(1.75,-2.5) 25(1.75,2.5) 26(1.25,2.5) 27(0.75,2.5) 28(0.25,2.5) 29(-0.25,2.5) 30(-0.75,2.5) 31(-1.25,2.5) 32(-1.75,2.5)
  rect 3.25x3.25 smd: 33(0,0)
QFN50P800X800X80-57M
  oval 0.9x0.3 smd: 1(-4,3.25) 2(-4,2.75) 3(-4,2.25) 4(-4,1.75) 5(-4,1.25) 6(-4,0.75) 7(-4,0.25) 8(-4,-0.25) 9(-4,-0.75) 10(-4,-1.25) 11(-4,-1.75) 12(-4,-2.25) 13(-4,-2.75) 14(-4,-3.25) 29(4,-3.25) 30(4,-2.75) 31(4,-2.25) 32(4,-1.75) 33(4,-1.25) 34(4,-0.75) 35(4,-0.25) 36(4,0.25) 37(4,0.75) 38(4,1.25) 39(4,1.75) 40(4,2.25) 41(4,2.75) 42(4,3.25)
  oval 0.3x0.9 smd: 15(-3.25,-4) 16(-2.75,-4) 17(-2.25,-4) 18(-1.75,-4) 19(-1.25,-4) 20(-0.75,-4) 21(-0.25,-4) 22(0.25,-4) 23(0.75,-4) 24(1.25,-4) 25(1.75,-4) 26(2.25,-4) 27(2.75,-4) 28(3.25,-4) 43(3.25,4) 44(2.75,4) 45(2.25,4) 46(1.75,4) 47(1.25,4) 48(0.75,4) 49(0.25,4) 50(-0.25,4) 51(-0.75,4) 52(-1.25,4) 53(-1.75,4) 54(-2.25,4) 55(-2.75,4) 56(-3.25,4)
  rect 6.7x6.7 smd: 57(0,0)
QFN80P400X400X80-13M
  oval 1.1x0.35 smd: 1(-1.9,0.8) 2(-1.9,0) 3(-1.9,-0.8) 7(1.9,-0.8) 8(1.9,0) 9(1.9,0.8)
  oval 0.35x1.1 smd: 4(-0.8,-1.9) 5(0,-1.9) 6(0.8,-1.9) 10(0.8,1.9) 11(0,1.9) 12(-0.8,1.9)
  rect 2.25x2.25 smd: 13(0,0)
RESC1005X50L
  rect 0.4x0.5 smd: 1(-0.45,0) 2(0.45,0)
RESC1608X90L
  rect 0.69x0.83 smd: 1(-0.67,0) 2(0.67,0)
SAMTEC_TSW-102-07-X-S
  rect 1.75x1.75 hole 1.15: 1(0,0)
  round 1.75 hole 1.15: 2(2.54,0)
SAMTEC_TSW-103-07-T-S
  rect 1.75x1.75 hole 1.15: 1(0,0)
  round 1.75 hole 1.15: 2(2.54,0) 3(5.08,0)
SAMTEC_TSW-103-07-X-D
  rect 1.75x1.75 hole 1.15: 1(0,0)
  round 1.75 hole 1.15: 2(0,2.54) 3(2.54,0) 4(2.54,2.54) 5(5.08,0) 6(5.08,2.54)
SOP50P490X110-10M
  rect 1.6x0.3 smd: 1(-2.35,1) 2(-2.35,0.5) 3(-2.35,0) 4(-2.35,-0.5) 5(-2.35,-1) 6(2.35,-1) 7(2.35,-0.5) 8(2.35,0) 9(2.35,0.5) 10(2.35,1)
SOP65P490X110-8M
  rect 1.6x0.45 smd: 1(-2.35,0.975) 2(-2.35,0.325) 3(-2.35,-0.325) 4(-2.35,-0.975) 5(2.35,-0.975) 6(2.35,-0.325) 7(2.35,0.325) 8(2.35,0.975)
SOT50P160X90-3M
  rect 1.05x0.4 smd: 1(-0.9,0.5) 2(-0.9,-0.5) 3(0.9,0)
SOT65P210X110-5M
  rect 1.1x0.45 smd: 1(-1.2,0.65) 2(-1.2,0) 3(-1.2,-0.65) 4(1.2,-0.65) 5(1.2,0.65)
SOT95P237X112-3M
  oval 1.6x0.65 smd: 1(-1.1,0.95) 2(-1.1,-0.95) 3(1.1,0)
SOT95P280X145-5M
  rect 1.25x0.65 smd: 1(-1.45,0.95) 2(-1.45,0) 3(-1.45,-0.95) 4(1.45,-0.95) 5(1.45,0.95)
SULLINS_PXC08SAAN
  rect 1.75x1.75 hole 1.15: 1(0,0)
  round 1.75 hole 1.15: 2(2.54,0) 3(5.08,0) 4(7.62,0) 5(10.16,0) 6(12.7,0) 7(15.24,0) 8(17.78,0)
SW_CL-SB-12B-1X
  round 0.8 hole 0.9 unplated: (0,3.4) (0,-3.4)
  rect 1.4x1.2 smd: 1(-2.2,2.5) 2(2.2,0) 3(-2.2,-2.5)
SW_EVQ-Q2X03W
  rect 3.2x1 smd: 1(-3.4,-2.5) 2(3.4,-2.5) 3(-3.4,2.5) 4(3.4,2.5)
TP_180P120D460H
  round 1.6 hole 1: 1(0,0)
TP_C240H180
  round 2.4 hole 1.8: 1(0,0)
TRAN_IRF_PQFN8_SINGLE_B
  rect 0.77x0.39 smd: 1(-1.54,0.975) 2(-1.54,0.325) 3(-1.54,-0.325) 4(-1.54,-0.975) 6(1.54,-0.325) 7(1.54,0.325) 8(1.54,0.975)
  custom 0.635x0.635 smd: 5(1.54,-0.975)
unnamed#2
  round 5.08 hole 3.175: (0,0)
XTAL320X250X070M
  rect 1.4x1.2 smd: 1(-1.1,-0.8) 2(1.1,-0.8) 3(1.1,0.8) 4(-1.1,0.8)

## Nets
+1.8V: C111.2 J101.2 R160.1 U103.5
+2.5V: C113.2 C151.1 R156.1 U100.40 U104.5
+3.3V: C115.2 C150.1 C157.2 C158.2 C221.2 C222.2 D100.A D101.A D102.A D103.A J100.2 J101.4 R11.1 R100.2 R118.2 R158.1 R163.2 R214.1 R283.1 R299.2 R300.1 U100.2 U100.22 U102.5 U107.11 U205.6(VDDIO) U205.7
AMUX: AMUX.1(TP1) R285.1 U1.A3
BATT: BATT.1(TP1) C2.1 C15.2 J9.1 U1.C1
BATTN: BATTN.1(TP1) J4.2 J9.2
CHGIN: C1.2 CHGIN.1(TP1) J1.1 J3.1 U1.A1
CTSN: U100.39 U101.8
DCDN: U100.25 U101.7
DSRN: U100.24 U101.6
DTRN: U100.28 U101.31
GROUND: C1.1 C2.2 C3.1 C4.1 C5.1 C6.1 C7.1 C8.1 C9.1 C10.2 C11.1 C12.1 C14.1 C15.1 C108.1 C110.1 C111.1 C112.1 C113.1 C114.2 C115.1 C118.1 C120.1 C129.1 C134.1 C150.2 C151.2 C152.1 C153.1 C154.1 C155.2 C156.1 C157.1 C158.1 C159.2 C217.2 C218.1 C220.1 C221.1 C222.1 C223.1 C234.1 C235.1 C237.1 C242.1 C244.2 C249.1 C251.1 GND1.1 GND2.1 GND3.1 GND4.1 J1.5 J2.3 J4.1 J8.5 J100.8 Q1.2(S) Q206.2(S) R4.2 R10.2 R12.3 R13.2 R110.2 R115.2 R122.2 R157.2 R159.2 R161.2 R165.2 R211.1 R252.1 R255.2 R257.2 R258.2 R260.2 R287.2 RT1.2 SW1.4 SW2.3 U1.C3 U1.D1 U100.1 U100.3 U100.4 U100.23 U100.35 U101.4 U101.17 U101.20 U101.24 U101.26 U101.33 U102.2 U103.2 U104.2 U107.5 U107.13 U108.2 U203.4 U205.8 U209.7 U210.2 Y101.2 Y101.4
INLDO: C7.2 C8.2 INLDO.1(TP1) R14.1 U1.D4
LDO: C4.2 C9.2 C11.2 C12.2 J101.6 J207.2 LDO.1(TP1) R2.1 U1.D5
LDO_ADC: C220.2 R259.2 R260.1 U209.2
MAXQP03: U100.52
MAXQP05: U100.54
NENLDO: J5.2 NEN.1(TP1) Q1.3 U1.A4
NIRQ: NIRQ.1(TP1) R9.2 R150.2 U1.A5
NIRQ1: J100.7 R152.1 U100.49
P01: R132.1 U100.50
P02: U100.51
P04: U100.53
P06: U100.55
P07: U100.56
PMLDO: J2.2 R133.2 U1.B3
PMLDO1: J100.6 R132.2 U107.7
POKLDO: J6.2 J6.4 J6.6 J100.5 POKLDO.1(TP1) U1.B4
REF_1: C244.1 R279.2 U209.4
RIN: U100.27 U101.3
RTSN: U100.26 U101.32
RXD: U100.43 U101.2
SCL: C134.2 R107.2 R136.2 SCL.1(TP1) U1.C5
SCL1: J100.3 R118.1 R155.2 R162.1 R213.1 R304.1 U107.9
SDA: C129.2 R108.2 R135.2 SDA.1(TP1) U1.B5
SDA1: J100.4 R100.1 R148.2 R164.2 R212.1 R303.1 U107.10
SINK1: R7.2 SINK1.1(TP1) U1.D2
SINK2: R8.2 SINK2.1(TP1) U1.D3
SYS: C6.2 R5.1 R14.2 SYS.1(TP1) U1.B1
TBIAS: R1.1 R12.1 R15.1 TBIAS.1(TP1) U1.C2
THM: J7.2 J7.4 J7.6 THM.1(TP1) U1.B2
TXD: U100.44 U101.30
UNNAMED_1_10103592-0001LF_I54_SHIELD10: J1.6 J1.7 J1.8 J1.9(SHIELD9) J1.10 J1.11 R3.1 R4.1
UNNAMED_1_CL-SB-12B-1X_I3_1: J5.1 SW2.1 SW2.2
UNNAMED_1_EKCAPNP_I52_1: C10.1 R3.2
UNNAMED_1_EVQ-Q2XXXX_I6_1: J5.3 SW1.1
UNNAMED_1_HEADER3PX2R_I85_1: J7.1 R12.2
UNNAMED_1_HEADER3PX2R_I85_3: J7.3 R1.2 RT1.1
UNNAMED_1_HEADER3PX2R_I85_5: J7.5 R13.1 R15.2
UNNAMED_1_HEADER3PX2R_I97_1: J6.1 R2.2
UNNAMED_1_HEADER3PX2R_I97_3: J6.3 R6.2
UNNAMED_1_HEADER3PX2R_I97_5: J6.5 R11.2
UNNAMED_1_LED4P_I66_A1: D1.1 D1.2 IN_SINK.1(TP1) R5.2
UNNAMED_1_LED4P_I66_K1: D1.3 R7.1
UNNAMED_1_LED4P_I66_K2: D1.4(K2) R8.1
UNNAMED_1_RESSMD_I84_1: EN_EXT.1(TP1) Q1.1 R10.1
UNNAMED_4_24AA02_I200_SCL: R162.2 U108.1
UNNAMED_4_24AA02_I200_SDA: R164.1 U108.3
UNNAMED_4_24AA02_I200_VCC: C14.2 R163.1 U108.4
UNNAMED_4_24AA02_I200_WP: R165.1 U108.5(WP)
UNNAMED_4_10103592-0001LF_I2_1: C155.1 FB100.1 J8.1
UNNAMED_4_10103592-0001LF_I2_2: J8.2 R123.1
UNNAMED_4_10103592-0001LF_I2_3: J8.3 R103.1
UNNAMED_4_10103592-0001LF_I2_SHIELD10: J8.6 J8.7 J8.8 J8.9(SHIELD9) J8.10 J8.11 R122.1 R142.1
UNNAMED_4_CAPNP_I101_2: C153.2 U100.41 Y101.3(P2)
UNNAMED_4_CAPNP_I105_2: C152.2 U100.42 Y101.1
UNNAMED_4_EKCAPNP_I12_1: C156.2 C159.1 U101.1(VCCIO) U101.16
UNNAMED_4_EKCAPNP_I29_1: C114.1 R142.2
UNNAMED_4_EKRESSMD_I15_2: R123.2 U101.15
UNNAMED_4_EKRESSMD_I16_2: R103.2 U101.14
UNNAMED_4_EKRESSMD_I17_1: R111.1 U101.22
UNNAMED_4_EKRESSMD_I17_2: D100.K(B) R111.2
UNNAMED_4_EKRESSMD_I18_1: R109.1 U101.21
UNNAMED_4_EKRESSMD_I18_2: D101.K(B) R109.2
UNNAMED_4_EKRESSMD_I87_1: R150.1 U107.3
UNNAMED_4_EKRESSMD_I109_1: R155.1 U100.36
UNNAMED_4_EKRESSMD_I113_1: R148.1 U100.37
UNNAMED_4_EKRESSMD_I153_1: R135.1 U107.1
UNNAMED_4_EKRESSMD_I154_1: R136.1 U107.2
UNNAMED_4_EKRESSMD_I171_2: R143.2 U107.6
UNNAMED_4_EKRESSMD_I174_1: R156.2 R157.1 U104.4
UNNAMED_4_EKRESSMD_I177_1: R158.2 R159.1 U102.4
UNNAMED_4_EKRESSMD_I190_2: R151.2 R152.2 U107.8
UNNAMED_4_EKRESSMD_I210_1: R133.1 U107.4
UNNAMED_4_LED_I7_B: D102.K(B) R110.1
UNNAMED_4_LED_I189_B: D103.K(B) R151.1
UNNAMED_4_MAX8512_I5_FB: R160.2 R161.1 U103.4
UNNAMED_6_CAPNP_I245_2: C249.2 R285.2 U209.1
UNNAMED_6_CAPNP_I341_2: C218.2 R252.2 R254.1 R299.1 U203.5
UNNAMED_6_CAPNP_I345_1: C219.1 R249.2 R253.1 U203.7(OUTB)
UNNAMED_6_CAPNP_I345_2: C219.2 R253.2 R255.1 R300.2 U203.6
UNNAMED_6_CAPNP_I357_2: C251.2 R250.2 U203.3
UNNAMED_6_EKCAPNP_I203_2: C223.2 U205.10
UNNAMED_6_EKCAPNP_I214_2: C237.2 R286.2 U209.8(VDD)
UNNAMED_6_EKCAPNP_I332_2: C242.2 J207.1 Q203.5 Q203.6 Q203.7 Q203.8 R259.1
UNNAMED_6_EKCAPNP_I355_1: C216.1 R249.1 U203.2
UNNAMED_6_EKCAPNP_I355_2: C216.2 R248.1
UNNAMED_6_EKCAPNP_I456_2: C235.2 R279.1 U210.5(OUT)
UNNAMED_6_EKCAPNP_I459_2: C234.2 R277.2 R280.1 U210.4
UNNAMED_6_EKRESSMD_I207_2: R214.2 U205.2
UNNAMED_6_EKRESSMD_I222_2: R283.2 U205.1
UNNAMED_6_EKRESSMD_I340_2: Q203.1 Q203.2 Q203.3(S3) R254.2 R258.1 SNS.1(TP1)
UNNAMED_6_EKRESSMD_I347_1: R248.2 R251.1 U203.1
UNNAMED_6_EKRESSMD_I347_2: J206.1 R251.2
UNNAMED_6_EKRESSMD_I450_2: R213.2 U205.4
UNNAMED_6_EKRESSMD_I451_2: R212.2 U205.5
UNNAMED_6_EKRESSMD_I452_2: R303.2 U209.6
UNNAMED_6_EKRESSMD_I453_2: R304.2 U209.5
UNNAMED_6_EKRESSMD_I460_2: R280.2 U210.3
UNNAMED_6_EKRESSMD_I469_2: R211.2 U205.3
UNNAMED_6_EKRESSMD_I472_1: R210.1 U205.9
UNNAMED_6_EKRESSMD_I472_2: R210.2 R250.1
UNNAMED_6_HEADER2P_I448_2: J206.2 Q203.4 R257.1
UNNAMED_6_RESSMD_I363_2: Q205.1 Q206.3 R288.2
VADC: Q205.2(S) R277.1 R286.1 R288.1
VIO: C5.2 C120.2 J2.1 J101.1 J101.3 J101.5 R6.1 R9.1 R107.1 R108.1 R143.1 U1.C4 U107.12(VL) VIO.1(TP1)
VL: C3.2 U1.A2(VL) VL.1(TP1)
VUSB: C108.2 C110.2 C112.2 C118.2 C154.2 C217.1 FB100.2 J3.2 J100.1 Q205.3 Q206.1 R115.1 R287.1 U101.19 U102.1 U102.3(SHDN*) U103.1 U103.3(SHDN*) U104.1 U104.3(SHDN*) U203.8

Pads without a net: J1 2 3 4; J8 4; SW1 2 3; U100 5 6 7 8 9 10 11 12 13 14 15 16 17 18 19 20 21 29 30 31 32 33 34 38 45 46 47 48 57; U101 5 9 10 11 12 13 18 23 25 27 28 29; U209 3; U210 1

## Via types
v1: diameter 0.457, hole 0.203, TOP to BOTTOM, 273 vias
v2: diameter 0.254, hole 0.127, TOP to BOTTOM, 12 vias

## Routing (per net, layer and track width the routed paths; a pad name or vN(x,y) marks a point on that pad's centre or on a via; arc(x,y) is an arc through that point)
+1.8V: length 32.4
  INTERNAL3 w0.508: v1(31.07,67.62) v1(31.07,57.53)
  BOTTOM w0.254: v1(31.07,57.53) 30.72,57.53 30.4,57.21 R160.1
  BOTTOM w0.381: U103.5 31.16,56.98 C111.2 31.07,56.92 v1(31.07,57.53)
  BOTTOM w0.508: v1(31.07,67.62) 16.69,67.62 J101.2
+2.5V: length 12.9
  TOP w0.381: v1(23.87,51.02) v1(30.06,51.02)
  BOTTOM w0.254: C151.1 v1(23.87,51.02) 24.04,50.85 U100.40 ; R156.1 29.34,49.34 29.84,49.84 C113.2
  BOTTOM w0.381: v1(30.06,51.02) 30.06,49.84 C113.2 30.37,49.84 30.48,49.73 U104.5
+3.3V: length 234.7
  TOP w0.254: v1(68.04,17.38) 63.71,17.38 v1(63.42,17.67)
  TOP w0.381: R11.1 41.26,63.77 43.02,65.53 46.3,65.53 ; 46.3,65.53 46.3,65.54 v1(46.5,65.54) ; 46.3,65.53 v1(52.21,65.53)
  TOP w0.508: D103.A v1(59.06,43.53) ; v1(12.07,64.67) 13.52,64.67 D101.A 15.49,64.63 15.51,64.62 D100.A 18.43,64.62 18.44,64.63 D102.A 19.82,64.63 19.83,64.62 v1(20.39,64.62) ; v1(20.39,59.66) v1(38.3,59.66) ; 38.65,63.77 38.63,63.76 v1(38.3,63.76) ; v1(63.42,17.67) 62.68,17.67 62.68,17.67 v1(59.54,17.67) ; v1(48.48,8.83) 58.69,8.83 58.87,8.65 v1(59.61,8.65) ; v1(52.21,65.53) 52.94,65.53 53.02,65.46 v1(59.06,65.46)
  INTERNAL3 w0.254: v1(15.84,40.58) v1(15.84,45.69)
  INTERNAL3 w0.381: J100.2 52.38,71.3 52.35,71.28 52.35,71.23 52.21,71.09 v1(52.21,65.53) ; v1(38.3,59.66) 38.63,59.33 v1(38.63,43.31) ; v1(46.5,62.06) v1(46.5,65.54) ; v1(19.82,54.21) 19.82,59.09 v1(20.39,59.66)
  INTERNAL3 w0.508: v1(20.39,64.62) 20.39,63.88 20.39,63.87 v1(20.39,59.66) ; v1(59.61,8.65) 59.61,11.22 59.54,11.3 v1(59.54,12.03) v1(59.54,17.67) 59.54,41.43 59.06,41.9 v1(59.06,43.53) v1(59.06,65.46) ; J101.4 v1(12.07,64.67) ; v1(19.82,54.21) v1(19.82,40.57) ; v1(38.3,59.66) v1(38.3,63.76)
  BOTTOM w0.254: C221.2 C222.2 49.06,10.14 49.08,10.12 U205.7 ; C221.2 48.62,9.3 48.95,9.62 U205.6 ; C221.2 v1(48.48,8.83) ; C158.2 v1(20.39,59.66) ; C158.2 21.02,59.16 21.06,59.13 U102.5 ; C158.2 20.31,59.08 20.09,59.08 19.8,58.79 19.8,57.79 19.8,57.79 R158.1 ; v1(68.04,17.38) 67.75,17.67 R300.1 ; C115.2 47.51,62.87 C157.2 ; v1(63.42,17.67) 63.96,17.67 R299.2 ; U100.2 24.54,40.91 24.21,40.58 16.58,40.58 ; C150.1 15.83,45.7 v1(15.84,45.69) 16.33,46.18 U100.22
  BOTTOM w0.381: R214.1 57.96,12.05 R283.1 58.6,12.05 58.62,12.03 v1(59.54,12.03) ; v1(19.82,54.21) 21.15,54.21 R118.2 22.07,54.2 R100.2 ; U107.11 v1(46.5,62.06) 46.54,62.11 C115.2 ; R163.2 v1(38.63,43.31)
  BOTTOM w0.508: v1(15.84,40.58) 16.58,40.58 16.59,40.57 v1(19.82,40.57)
AMUX: length 59.3
  TOP w0.203: v1(40.47,39.41) 40.47,38.37 40.49,38.36 40.49,37.71 40.48,37.7 40.48,37.44 39.14,36.1 U1.A3
  INTERNAL3 w0.203: AMUX.1 57.1,20.45 58.57,21.92 v1(58.57,26.65)
  INTERNAL3 w0.254: v1(58.5,39.39) 58.5,38.78 58.57,38.71 v1(58.57,26.65)
  BOTTOM w0.254: v1(40.47,39.41) 41.08,39.41 41.11,39.39 v1(58.5,39.39) ; R285.1 v1(58.57,26.65)
BATT: length 10.7
  TOP w0.203: 38.02,35.09 38.03,35.1 U1.C1
  TOP w0.254: C2.1 36.76,34.41 37.06,34.41 37.75,35.09 38.02,35.09
  TOP w0.635: J9.1 11.66,21.25 BATT.1
CHGIN: length 23
  TOP w0.203: U1.A1 38.34,35.9 38.33,35.89 38.17,36.06
  TOP w0.254: C1.2 37.17,37.37 37.33,37.21 37.35,37.21 37.99,36.57 37.99,36.24 38.17,36.06
  TOP w0.381: 7.29,36.34 5.38,36.34 5.38,36.34 5.37,36.35 J1.1
  TOP w0.635: CHGIN.1 11.92,36.34 7.29,36.34
  BOTTOM w1.016: v1(7.7,36.37) 7.11,36.96 7.11,43.25 J3.1
CTSN: length 16.4
  TOP w0.254: v1(12.18,51.44) v1(22.85,51.44)
  BOTTOM w0.254: U101.8 v1(12.18,51.44) ; v1(22.85,51.44) 23.29,51.01 23.29,50.76 23.54,50.51 U100.39
DCDN: length 12.1
  BOTTOM w0.254: U100.25 16.95,47.68 16.94,47.67 13.88,47.67 12.68,48.87 U101.7
DSRN: length 12.2
  INTERNAL3 w0.254: v1(14.24,47.15) v1(14.24,48.39)
  BOTTOM w0.254: v1(14.24,47.15) 14.85,47.15 14.88,47.18 U100.24 ; U101.6 13.18,50.36 13.22,50.32 13.22,49.42 v1(14.24,48.39)
DTRN: length 8.5
  BOTTOM w0.254: U100.28 17.79,56.14 17.31,56.61 16.43,56.61 U101.31
GROUND: length 82.4
  TOP w0.203: v1(66.43,18.11) v1(69.83,18.11)
  TOP w0.254: R110.2 v1(21.92,63.76) ; SW2.3 v1(74.18,67.31) ; 19.49,8.13 v1(19.49,9.49) ; RT1.2 v1(23.3,5.76) ; SW1.4 v1(61.04,68.39) ; v1(60.19,47.65) R10.2 60.95,47.55 Q1.2
  TOP w0.381: R4.2 7.32,38.94 5.38,38.94 5.38,38.94 5.37,38.95 J1.5 ; 7.54,61.15 6.97,60.58 J8.5 ; v1(40.87,32.83) 40.87,32.86 40.87,32.86 C4.1
  TOP w0.508: C6.1 36.37,36.64 35.36,36.64 v1(35.27,36.73) ; C10.2 8.96,39.2 R4.2
  INTERNAL3 w0.152: v2(39.14,35.1) 39.14,34.98 38.86,34.7 38.8,34.7 38.79,34.7 v2(38.34,34.7)
  BOTTOM w0.203: R255.2 v1(66.43,18.11) ; v1(69.83,18.11) 69.83,19.99 69.66,20.16 R258.2
  BOTTOM w0.254: U101.17 12.18,60.82 12.15,60.86 v1(12.15,61.09) ; 30.39,53.04 v1(30.39,53.1) R161.2 ; 46.5,56.45 v1(46.5,56.47) U107.5 U107.13 ; Q206.2 46.56,13.97 47.28,14.69 R287.2 v1(48.16,14.69) 48.16,14.69 ; R257.2 v1(72.21,13.63) ; v1(31.75,56.17) 31.59,56.01 C111.1 ; C234.1 v1(53.87,13.88) ; 13.92,54.37 v1(13.92,54.37) 14.18,54.64 U101.4 14.18,57.61 U101.33 ; v1(37.84,56.1) 37.81,56.13 C110.1 36.21,56.13 36.02,56.33 U103.2 ; v1(19.28,56.32) 19.3,56.3 R159.2 ; C151.2 v1(23.33,52.32) ; Y101.2 24.54,53.83 C153.1 24.45,53.49 v1(24.86,53.09) ; U210.2 v1(55.35,17.44) ; C217.2 v1(69.27,11.73) ; U100.23 15.84,46.68 15.76,46.6 C150.2 14.57,46.6 v1(14.41,46.43) ; U209.7 48.5,24.84 48.44,24.9 C237.1 v1(47.04,24.9) 47.04,24.9 ; C156.1 12.49,62.63 12.51,62.64 12.98,62.64 13.56,62.06 C108.1 13.68,61.72 U101.20 ; v1(28.23,56.46) 28.22,56.45 Y101.4 ; U100.35 21.54,50.38 21.13,50.79 v1(20.56,50.79) ; C218.1 v1(63.86,15.42) ; U101.26 v1(17.74,59.11) ; U100.1 v1(25.72,41.93) ; R260.2 57.94,24.55 C220.1 58.08,25.71 C249.1 ; U100.3 24.04,41.34 v1(23.81,41.11) 23.54,41.38 U100.4 ; U101.24 v1(16.41,60.36) ; R157.2 v1(28.79,47.21) ; C152.1 v1(25.87,51.59) ; C158.1 v1(20.39,57.79) ; C235.1 v1(49.55,17.03) ; R252.1 v1(63.82,14.56)
  BOTTOM w0.381: U102.2 25.35,58.48 25.62,58.2 C118.1 v1(26.33,57.66) ; R211.1 58.86,10.24 v1(58.86,10.25) ; R115.2 v1(6.36,52.96) ; C157.1 47.51,63.77 C115.1 ; C114.2 v1(7.48,61.26) ; U104.2 35.25,49.08 35.49,48.84 C112.1 v1(36.85,48.84) ; C154.1 v1(6.39,53.95) ; C155.2 v1(9.06,55.47) ; C113.1 v1(30.69,48.94)
  BOTTOM w0.635: C114.2 8.34,62.26 R122.2 v1(7.45,62.45)
  vias: v1(7.46,61.84) v1(7.48,60.66) v1(8.3,38.49) v1(9.2,38.49) v1(9.57,53.73) v1(10.12,39.22) v1(10.12,38.48) v1(10.99,39.23) v1(11.43,63.2) v1(16.35,26.38) v1(16.35,25.8) v1(18.41,26.39) v1(18.41,25.82) v1(31.07,24.19) v1(31.08,23.62) v1(31.66,24.18) v1(31.67,23.62) v1(32.41,36.31) v1(32.97,36.74) v1(33.68,36.29) v1(34.15,36.77) v1(34.81,36.29) v1(36.26,29.87) v1(36.27,29.21) v1(36.44,33.01) v1(36.93,29.89) v1(36.96,29.24) v1(37.69,39.49) v1(37.72,38.98) v1(38.3,39.46) v1(38.33,38.96) v1(39.02,38.87) v1(40.15,32.83) v1(41.35,32.58) v1(41.96,32.58) v1(42.38,35.55) v1(43.15,31.15) v1(43.17,30.63) v1(43.51,40.18) v1(43.75,31.11) v1(43.78,30.62) v1(44.22,40.74) v1(44.22,40.17) v1(44.95,40.71) v1(47.26,62.22) v1(47.42,8.21) v1(47.43,6.78) v1(48.5,8.21) v1(48.51,6.8) v1(55.74,21.86) v1(55.75,20.87) v1(58.07,25.21) v1(65.45,27.45) v1(66.4,27.45) v1(67.43,27.43) v1(69.14,1.83) v1(70.04,28.43) v1(70.74,39.19) v1(70.82,34.68) v1(75.13,46.15) v2(38.11,34.54) v2(38.12,34.19) v2(38.36,34.37)
INLDO: length 33.4
  TOP w0.203: C7.2 39.54,33.6 U1.D4
  TOP w0.508: C7.2 39.33,33.25 R14.1
  TOP w0.635: 39.33,30.77 R14.1
  TOP w0.762: INLDO.1 44.74,15.18 39.33,20.59 39.33,30.77
LDO: length 120.2
  TOP w0.203: 40.77,33.87 U1.D5
  TOP w0.381: C4.2 44.34,33.32 ; R2.1 24.55,63.82 v1(24.04,64.34)
  TOP w0.508: v1(24.04,68.71) 17.67,68.71 16.6,67.65 11.58,67.65 J101.6
  TOP w0.635: 44.34,33.32 47.87,29.79 66.09,29.79 LDO.1
  TOP w1.27: LDO.1 70.46,31.04 70.64,31.22 J207.2
  INTERNAL3 w0.381: v1(24.04,64.34) v1(24.04,68.71) ; v1(52.7,64.54) 52.7,52.38 52.71,52.38 v1(52.71,32.07)
  BOTTOM w0.381: v1(24.04,64.34) 24.71,64.34 24.95,64.57 51.8,64.57 51.84,64.54 v1(52.7,64.54)
LDO_ADC: length 4.2
  BOTTOM w0.254: R259.2 57.04,22.85 R260.1 56.87,23.95 C220.2 56.1,24.69 55.96,24.84 U209.2
NENLDO: length 47.7
  TOP w0.152: NEN.1 48.62,45.13 48.12,44.63 v1(41.82,44.63) ; U1.A4 39.54,36.05 41.42,37.94 41.42,38.22 v1(41.82,38.62)
  TOP w0.254: Q1.3 v1(67.27,48.05) 67.88,48.05 68.01,47.92 J5.2
  INTERNAL3 w0.152: v1(41.82,38.62) v1(41.82,44.63)
  INTERNAL3 w0.254: v1(67.27,48.05) 67.27,46.34 67.25,46.31 NEN.1
NIRQ: length 48.9
  TOP w0.152: U1.A5 42,37.96 v1(51.03,37.96) 51.59,37.96 51.62,37.99 51.84,37.99 54.37,40.52 63.28,40.52 63.38,40.42 R9.2 64.63,40.42 64.7,40.5 NIRQ.1
  INTERNAL3 w0.254: v1(51.03,56.61) v1(51.03,37.96)
  BOTTOM w0.254: v1(51.03,56.61) 51.03,57.44 R150.2
NIRQ1: length 73.5
  INTERNAL3 w0.254: v1(34.59,69.85) 34.59,65.68 33.56,64.65 v1(33.56,60.35) 33.56,46.88 33.43,46.75 v1(33.43,46.14) ; v1(65.01,69.85) 65.01,71.29 65.08,71.37 J100.7
  BOTTOM w0.254: R152.1 41.36,60.26 41.27,60.35 v1(33.56,60.35) ; U100.49 32.78,46.18 32.82,46.14 v1(33.43,46.14) ; v1(34.59,69.85) v1(65.01,69.85)
P01: length 3.5
  BOTTOM w0.254: R132.1 28.54,45.39 28.25,45.68 U100.50
PMLDO: length 46
  TOP w0.203: v1(41.06,55.8) 48.43,55.8 48.5,55.87 48.56,55.87 v1(48.65,55.78)
  INTERNAL3 w0.203: J2.2 41.28,71 41.06,70.79 v1(41.06,55.8) 41.06,37.2 39.79,35.93 39.44,35.93 39.14,35.62 v2(39.14,35.5)
  BOTTOM w0.254: v1(48.65,55.78) 48.59,55.72 48.23,55.72 R133.2
PMLDO1: length 67
  TOP w0.254: v1(43.64,42.24) v1(30.06,42.24)
  INTERNAL3 w0.254: v1(62.54,69.19) 62.54,71.37 62.54,71.37 J100.6 ; v1(30.06,42.24) v1(30.06,44.65) ; v1(43.64,42.24) v1(43.64,58.48) v1(43.64,69.19)
  BOTTOM w0.254: U107.7 v1(43.64,58.48) ; v1(43.64,69.19) v1(62.54,69.19) ; R132.2 30.06,45.35 v1(30.06,44.65)
POKLDO: length 102.7
  TOP w0.254: v1(42.06,37.27) 42.67,37.27 42.68,37.26 56.97,37.26 56.99,37.27 v1(57.6,37.27) 58.21,37.27 58.24,37.3 63.1,37.3 64.73,35.67 POKLDO.1 ; J6.2 J6.4 J6.6 v1(35.96,72.11)
  INTERNAL3 w0.152: v1(42.06,37.27) 40.28,35.5 v2(39.54,35.5)
  INTERNAL3 w0.254: 59.36,67.09 57.6,65.32 v1(57.6,37.27) ; 59.36,67.09 v1(59.36,67.05) ; 59.36,67.09 60,67.72 J100.5 ; v1(35.96,72.11) v1(35.96,67.05)
  BOTTOM w0.254: v1(35.96,67.05) v1(59.36,67.05)
REF_1: length 5.2
  BOTTOM w0.254: U209.4 54.7,22.93 ; 54.7,22.93 54.7,21.86 C244.1 ; 54.7,22.93 54.73,22.91 54.73,21.34 53.95,20.56 R279.2
RIN: length 9.7
  TOP w0.254: v1(16.95,54.37) v1(14.69,54.37)
  BOTTOM w0.254: v1(14.69,54.37) 14.69,55.35 U101.3 ; U100.27 17.12,48.68 16.95,48.84 v1(16.95,54.37)
RTSN: length 9.1
  BOTTOM w0.254: U101.32 16.43,48.47 16.72,48.19 16.87,48.19 16.89,48.18 U100.26
RXD: length 18.5
  TOP w0.254: v1(15.18,49.87) 26.21,49.87 v1(26.86,49.22)
  BOTTOM w0.254: v1(26.86,49.22) 25.82,49.22 U100.43 ; U101.2 v1(15.18,49.87)
SCL: length 83.5
  TOP w0.152: v1(69.61,36.04) C134.2 71.29,36.04 71.93,35.41 SCL.1 72.4,33.74 68.9,33.74 68.61,34.02 64.67,34.02 62.37,36.32 41.43,36.32 40.21,35.1 U1.C5
  INTERNAL3 w0.254: v1(69.3,59.2) 69.3,36.96 69.61,36.65 v1(69.61,36.04)
  BOTTOM w0.254: v1(69.3,59.2) R136.2 51.06,59.2 R107.2
SCL1: length 147.9
  TOP w0.254: v1(46.1,23.09) v1(61.1,23.09) ; v1(54.94,62.88) v1(44.68,62.88) ; v1(21.14,52.78) 22.92,54.55 v1(54.88,54.55)
  INTERNAL3 w0.254: v1(54.94,46.35) 54.94,53.75 54.88,53.81 v1(54.88,54.55) 54.88,55.21 54.94,55.27 v1(54.94,62.88) 54.94,71.84 54.89,71.89 54.89,72.6 J100.3 ; v1(61.35,46.28) 61.35,45.04 61.09,44.79 61.09,24.81 61.1,24.8 v1(61.1,23.09) 61.1,9.72 v1(61.51,9.31)
  BOTTOM w0.254: 54.64,46.28 48.47,46.28 47.29,47.46 46.48,47.46 46.46,47.47 R162.1 ; 54.64,46.28 v1(61.35,46.28) ; 54.64,46.28 54.71,46.35 v1(54.94,46.35) ; v1(44.68,62.88) 44.68,62.27 44.6,62.19 U107.9 ; R304.1 v1(46.1,23.09) ; R213.1 58.52,9.25 58.59,9.31 v1(61.51,9.31)
  BOTTOM w0.381: R155.2 v1(21.14,52.78) 21.16,52.8 R118.1
SDA: length 84.3
  TOP w0.152: v1(72.17,34.24) 68.91,34.24 68.75,34.39 65.05,34.39 62.74,36.7 41.3,36.7 40.1,35.5 U1.B5 ; SDA.1 71.31,40.57 71.31,40.57 C129.2
  TOP w0.254: C129.2 70.76,40.6 v1(70.76,41.46)
  INTERNAL3 w0.152: SDA.1 72.17,38.73 v1(72.17,34.24)
  INTERNAL3 w0.254: v1(70.76,41.46) 70.76,41.55 70.01,42.31 v1(70.01,60.69)
  BOTTOM w0.254: R135.2 51.05,60.68 R108.2 v1(70.01,60.69)
SDA1: length 147.4
  TOP w0.254: v1(22.08,52.76) 22.85,52.76 23.98,53.88 55.99,53.88 56.01,53.87 v1(56.62,53.87) ; v1(45.7,63.63) 55.95,63.63 56.01,63.58 v1(56.62,63.58) ; v1(46.27,23.98) v1(60.48,23.98)
  INTERNAL3 w0.254: J100.4 57.46,67.01 56.62,66.16 v1(56.62,63.58) 56.62,54.83 56.62,54.82 v1(56.62,53.87) 56.62,53.01 56.62,53.01 v1(56.62,45.59) ; v1(60.48,7.66) v1(60.48,23.98) 60.48,24.58 60.55,24.66 v1(60.55,45.62)
  BOTTOM w0.254: v1(60.55,45.62) 56.37,45.62 ; 56.37,45.62 46.57,45.62 46.5,45.55 R164.2 ; 56.37,45.62 56.4,45.59 v1(56.62,45.59) ; R212.1 58.52,8.38 59.22,7.68 59.86,7.68 59.87,7.66 v1(60.48,7.66) ; U107.10 45.7,63.02 45.7,63.02 v1(45.7,63.63) ; R303.1 v1(46.27,23.98)
  BOTTOM w0.381: R100.1 22.09,52.76 v1(22.08,52.76) R148.2
SINK1: length 37
  TOP w0.203: U1.D2 38.74,34.69 38.74,34.2 38.11,33.57 38.11,32.11
  TOP w0.254: 38.11,32.11 38.11,28.23 35.08,25.2 R7.2 31.6,12.59 29.29,10.27 29.29,4.9 29.32,4.87 SINK1.1
SINK2: length 32.9
  TOP w0.203: U1.D3 39.14,34.02 38.83,33.71
  TOP w0.254: 38.83,33.71 38.52,33.41 38.52,27.84 37.52,26.84 R8.2 38.31,12.51 39.13,11.69 39.13,4.86 39.1,4.83 SINK2.1
SYS: length 15.3
  TOP w0.203: 38,35.5 U1.B1
  TOP w0.254: 38,35.5 37.38,35.5 37.38,35.47 37.18,35.28 C6.2 36.36,35.31 v1(35.44,35.31)
  TOP w0.635: R5.1 v1(32.77,10.18)
  INTERNAL3 w0.635: v1(32.77,10.18) v1(32.77,21.04)
  BOTTOM w0.508: v1(41.31,30.41) 41.28,30.37 40.67,30.37 v1(40.66,30.38)
  vias: v1(32.61,35.28) v1(32.62,34.34) v1(33.69,35.29) v1(33.7,34.36) v1(34.44,34.38) v1(34.64,35.29) v1(40.65,31.02) v1(41.32,31.04)
TBIAS: length 59.2
  TOP w0.203: 37.41,32.09 37.41,32.19 v2(37.75,32.53)
  TOP w0.254: R12.1 24.37,3.84 24.42,3.9 v1(26.51,3.9) ; TBIAS.1 15.33,5.77 21.69,5.77 22.06,6.14 R1.1 21.98,6.91 21.46,7.43 21.46,7.53 20.87,8.12 R15.1 20.78,9.01 20.75,9.05 v1(20.75,9.66)
  TOP w0.381: v1(26.51,9.66) 26.51,21.19 37.41,32.09
  INTERNAL3 w0.152: v2(38.74,35.1) 38.08,35.1 37.75,34.77 v2(37.75,32.53)
  INTERNAL3 w0.254: v1(26.51,9.66) v1(26.51,3.9)
  BOTTOM w0.254: v1(26.51,9.66) v1(20.75,9.66)
THM: length 40.1
  TOP w0.254: v2(37.36,32.94) 25.89,21.47 25.89,14.41 25.27,13.79 J7.2
  INTERNAL3 w0.152: v2(37.36,32.94) 37.36,34.81 38.05,35.5 38.28,35.5 38.28,35.5 v2(38.74,35.5)
  BOTTOM w0.254: THM.1 15.1,13.74 15.49,13.74 15.54,13.79 J7.6 J7.4 J7.2
TXD: length 24.6
  TOP w0.254: v1(15.83,49.04) 16.18,49.39 26.04,49.39 26.75,48.68 v1(27.85,48.68)
  INTERNAL3 w0.254: v1(15.83,49.04) 15.83,51.88 17.63,53.68 v1(17.63,57.17)
  BOTTOM w0.254: U100.44 v1(27.85,48.68) ; v1(17.63,57.17) 17.44,57.17 17.38,57.11 U101.30
UNNAMED_1_10103592-0001LF_I54_SHIELD10: length 20.4
  TOP w0.508: 2.25,36.55 2.25,38.58 ; 2.25,36.55 2.12,36.68 J1.10 ; 2.25,36.55 2.25,33.74 2.45,33.55 ; 2.25,38.58 2.45,38.78 2.45,41.74 ; 2.25,38.58 2.25,38.58 2.12,38.58 2.12,38.58 J1.11 ; R3.1 7.57,41.8 R4.1 7.54,40.5 5.97,40.5 5.53,40.07 ; J1.7 5.4,40.07 5.4,40.06 5.53,40.06 5.53,40.07 ; 2.45,33.55 2.45,33.54 4.13,35.22 5.53,35.22 5.53,35.22 J1.8 ; 2.45,33.55 J1.9 ; 2.45,41.74 4.13,40.07 5.53,40.07 ; 2.45,41.74 2.45,41.75 J1.6
UNNAMED_1_CL-SB-12B-1X_I3_1: length 17.7
  TOP w0.254: SW2.2 71.58,63.35 74.08,60.85 SW2.1 74.15,60.82 v1(74.15,59.36)
  INTERNAL3 w0.254: J5.1 71.66,52.41 71.66,56.87 v1(74.15,59.36)
UNNAMED_1_EKCAPNP_I52_1: length 1.3
  TOP w0.508: C10.1 8.98,40.54 R3.2
UNNAMED_1_EVQ-Q2XXXX_I6_1: length 19.5
  TOP w0.254: v1(71,58.23) 68.77,58.23 67.34,59.65 66.93,59.65 66.92,59.64 SW1.1
  INTERNAL3 w0.254: v1(71,58.23) 71,47.99 J5.3
UNNAMED_1_HEADER3PX2R_I85_1: length 28.3
  INTERNAL3 w0.254: v1(16.93,18.08) v1(16.93,1.32)
  BOTTOM w0.254: J7.1 22.26,18.08 v1(16.93,18.08) ; R12.2 19.51,1.3 19.5,1.32 v1(16.93,1.32)
UNNAMED_1_HEADER3PX2R_I85_3: length 10.2
  TOP w0.254: R1.2 23.3,8.13 RT1.1 23.3,12.06 22.81,12.55 22.81,15 J7.3
UNNAMED_1_HEADER3PX2R_I85_5: length 12.6
  TOP w0.254: J7.5 17.59,15 17.59,7.96 18.65,6.91 R13.1 20.77,6.91 R15.2
UNNAMED_1_HEADER3PX2R_I97_1: length 4.6
  TOP w0.254: J6.1 27.31,68.32 27.27,68.27 R2.2
UNNAMED_1_HEADER3PX2R_I97_3: length 4.6
  TOP w0.254: J6.3 29.85,68.32 29.82,68.28 R6.2
UNNAMED_1_HEADER3PX2R_I97_5: length 4.6
  TOP w0.254: R11.2 32.34,68.26 32.39,68.32 J6.5
UNNAMED_1_LED4P_I66_A1: length 10.7
  TOP w0.254: IN_SINK.1 36.04,5.66 D1.1 D1.2
  TOP w0.635: R5.2 32.77,5.06 IN_SINK.1
UNNAMED_1_LED4P_I66_K1: length 2.3
  TOP w0.254: R7.1 35.15,11.25 36.04,10.36 D1.3
UNNAMED_1_LED4P_I66_K2: length 2.2
  TOP w0.254: R8.1 37.45,11.17 36.83,10.55 36.83,10.48 36.74,10.38 D1.4
UNNAMED_1_RESSMD_I84_1: length 20.6
  TOP w0.254: Q1.1 61.48,48.55 61.48,48.55 R10.1 v1(60.85,49.1) ; v1(60.85,54.92) 72.21,54.92 72.28,54.99 EN_EXT.1
  INTERNAL3 w0.254: v1(60.85,49.1) v1(60.85,54.92)
UNNAMED_4_24AA02_I200_SCL: length 2.8
  BOTTOM w0.254: R162.2 44.4,47.47 44.39,47.46 U108.1
UNNAMED_4_24AA02_I200_SDA: length 2.8
  BOTTOM w0.254: R164.1 44.44,45.55 44.43,45.56 U108.3
UNNAMED_4_24AA02_I200_VCC: length 2.9
  BOTTOM w0.254: R163.1 37.73,44.81 37.74,44.82 C14.2 37.76,45.56 U108.4
UNNAMED_4_24AA02_I200_WP: length 1.5
  BOTTOM w0.254: U108.5 37.82,47.46 R165.1
UNNAMED_4_10103592-0001LF_I2_1: length 4.3
  TOP w0.381: J8.1 v1(7.95,57.98)
  BOTTOM w0.381: v1(7.95,57.98) 7.95,57.2 FB100.1 8.9,57.18 C155.1
UNNAMED_4_10103592-0001LF_I2_2: length 3.3
  TOP w0.254: J8.2 v1(6.87,58.63)
  BOTTOM w0.254: v1(6.87,58.63) 6.87,59.24 7.31,59.67 8.14,59.67 R123.1
UNNAMED_4_10103592-0001LF_I2_3: length 2.7
  TOP w0.254: v1(7.59,58.82) 7.12,59.28 J8.3
  BOTTOM w0.254: R103.1 8.16,58.82 v1(7.59,58.82)
UNNAMED_4_10103592-0001LF_I2_SHIELD10: length 21.4
  TOP w0.508: J8.8 4.38,56.86 J8.9 2.71,58.15 J8.10 J8.11 2.51,63.18 J8.6 4.38,61.71 J8.7
  BOTTOM w0.635: J8.7 5.79,62.81 6.78,63.79 R122.1 8.21,63.86 R142.1
UNNAMED_4_CAPNP_I101_2: length 7.6
  BOTTOM w0.254: U100.41 24.54,52.5 23.78,53.26 23.78,54.68 24.06,54.96 C153.2 24.92,55.43 Y101.3
UNNAMED_4_CAPNP_I105_2: length 6.1
  BOTTOM w0.254: U100.42 25.81,49.93 27.09,51.21 27.09,51.63 27.09,51.63 C152.2 27.85,52.3 28.22,52.68 Y101.1
UNNAMED_4_EKCAPNP_I12_1: length 18.1
  TOP w0.254: v1(15.72,53.04) 15.04,53.04 15.01,53.01 v1(11,53.01)
  INTERNAL3 w0.254: v1(10.63,60.05) 10.63,59.44 10.77,59.3 10.77,54.48 11,54.26 v1(11,53.01)
  BOTTOM w0.254: C156.2 11.42,61.15 11.43,61.14 U101.16 11.07,59.61 v1(10.63,60.05) ; C159.1 v1(11,53.01) ; U101.1 15.68,54.82 15.72,54.78 v1(15.72,53.04)
UNNAMED_4_EKCAPNP_I29_1: length 1.3
  BOTTOM w0.635: R142.2 9.68,62.46 C114.1
UNNAMED_4_EKRESSMD_I15_2: length 2.6
  BOTTOM w0.254: R123.2 9.84,59.7 10.43,59.11 U101.15
UNNAMED_4_EKRESSMD_I16_2: length 2.5
  BOTTOM w0.254: U101.14 9.87,58.61 9.65,58.83 R103.2
UNNAMED_4_EKRESSMD_I17_1: length 1.8
  BOTTOM w0.254: U101.22 14.68,60.82 15.29,61.43 15.29,61.62 R111.1
